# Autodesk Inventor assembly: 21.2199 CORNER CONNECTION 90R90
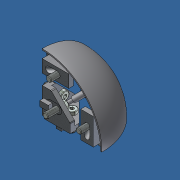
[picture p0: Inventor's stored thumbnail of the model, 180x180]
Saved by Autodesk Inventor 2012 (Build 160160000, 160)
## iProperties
Created: 2014-06
Part Number: 21.2199 CORNER CONNECTION 90R90
Document SubType Name: Assembly
Designer: Admin
Author: Admin
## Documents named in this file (7)
- C:\Andys Backup Data\ANDY'S INVENTOR\INVENTOR LIBRARIES\PARTS LIBRARY\FASTENING ELEMENTS\21.2199 CORNER CONNECTION 90R90.iam
- C:\Andys Backup Data\ANDY'S INVENTOR\INVENTOR LIBRARIES\PARTS LIBRARY\FASTENING ELEMENTS\SUBCOMPONENTS\22.0980_1 END CAP MW 90 R 90 GRAY.ipt
- C:\Andys Backup Data\ANDY'S INVENTOR\INVENTOR LIBRARIES\PARTS LIBRARY\FASTENING ELEMENTS\SUBCOMPONENTS\21.1708_2 ANGLE 45 DEG.ipt
- C:\Andys Backup Data\ANDY'S INVENTOR\INVENTOR LIBRARIES\PARTS LIBRARY\FASTENING ELEMENTS\SUBCOMPONENTS\21.1386 SCREW CON ANTI ROT.ipt
- C:\Andys Backup Data\ANDY'S INVENTOR\INVENTOR LIBRARIES\PARTS LIBRARY\FASTENING ELEMENTS\SCREWS CAP\21.1204 M8X25.ipt
- C:\Andys Backup Data\ANDY'S INVENTOR\INVENTOR LIBRARIES\PARTS LIBRARY\FASTENING ELEMENTS\SUBCOMPONENTS\21.2078_1 Angle 19.ipt
- C:\Andys Backup Data\ANDY'S INVENTOR\INVENTOR LIBRARIES\PARTS LIBRARY\FASTENING ELEMENTS\SCREWS CAP\21.1202 M8X20.ipt
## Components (17 placed, 6 different names)
1. 22.0980_1 END CAP MW 90 R 90 GRAY:1 — Mate:1, Flush:1
2. 21.1708_2 ANGLE 45 DEG:1 — Mate:1, Flush:1, Insert:1, Angle:1, Insert:2, Angle:2, Insert:3, Angle:3, Insert:4, Insert:5, Insert:6, Flush:2, Flush:3, Flush:4, Flush:5, Flush:6, Flush:7, Mate:22
3. 21.1386 SCREW CON ANTI ROT:1 — Insert:1, Angle:1
4. 21.1386 SCREW CON ANTI ROT:2 — Insert:3, Angle:3
5. 21.1386 SCREW CON ANTI ROT:3 — Insert:2, Angle:2
6. 21.1204  M8 x 25:1 — Insert:6
7. 21.1204  M8 x 25:2 — Insert:5, Mate:20, Mate:21
8. 21.1204  M8 x 25:3 — Insert:4
9. 21.2078_1 Angle 19:1 — Mate:14, Mate:15, Mate:16, Mate:17, Mate:18, Mate:19, Flush:4, Flush:5
10. 21.2078_1 Angle 19:2 — Mate:8, Mate:9, Mate:10, Mate:11, Mate:12, Mate:13, Flush:2, Flush:3
11. 21.2078_1 Angle 19:3 — Mate:2, Mate:3, Mate:4, Mate:5, Mate:6, Mate:7, Flush:6, Flush:7, Mate:22
12. 21.1202  M8 x 20:1 — Mate:5, Mate:6, Mate:7
13. 21.1202  M8 x 20:2 — Mate:14, Mate:16, Mate:19
14. 21.1202  M8 x 20:3 — Mate:15, Mate:17, Mate:18, Mate:21
15. 21.1202  M8 x 20:4 — Mate:11, Mate:12, Mate:13, Mate:20
16. 21.1202  M8 x 20:5 — Mate:2, Mate:3, Mate:4
17. 21.1202  M8 x 20:6 — Mate:8, Mate:9, Mate:10
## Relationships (38: Mate 22, Flush 7, Insert 6, Angle 3)
- Mate:1: 22.0980_1 END CAP MW 90 R 90 GRAY:1 ↔ 21.1708_2 ANGLE 45 DEG:1
- Flush:1: 22.0980_1 END CAP MW 90 R 90 GRAY:1 ↔ 21.1708_2 ANGLE 45 DEG:1
- Insert:1: 21.1708_2 ANGLE 45 DEG:1 ↔ 21.1386 SCREW CON ANTI ROT:1
- Angle:1: 21.1708_2 ANGLE 45 DEG:1 ↔ 21.1386 SCREW CON ANTI ROT:1
- Insert:2: 21.1708_2 ANGLE 45 DEG:1 ↔ 21.1386 SCREW CON ANTI ROT:3
- Angle:2: 21.1708_2 ANGLE 45 DEG:1 ↔ 21.1386 SCREW CON ANTI ROT:3
- Insert:3: 21.1708_2 ANGLE 45 DEG:1 ↔ 21.1386 SCREW CON ANTI ROT:2
- Angle:3: 21.1708_2 ANGLE 45 DEG:1 ↔ 21.1386 SCREW CON ANTI ROT:2
- Insert:4: 21.1708_2 ANGLE 45 DEG:1 ↔ 21.1204  M8 x 25:3
- Insert:5: 21.1708_2 ANGLE 45 DEG:1 ↔ 21.1204  M8 x 25:2
- Insert:6: 21.1708_2 ANGLE 45 DEG:1 ↔ 21.1204  M8 x 25:1
- Mate:2: 21.2078_1 Angle 19:3 ↔ 21.1202  M8 x 20:5
- Mate:3: 21.2078_1 Angle 19:3 ↔ 21.1202  M8 x 20:5
- Mate:4: 21.2078_1 Angle 19:3 ↔ 21.1202  M8 x 20:5
- Mate:5: 21.2078_1 Angle 19:3 ↔ 21.1202  M8 x 20:1
- Mate:6: 21.2078_1 Angle 19:3 ↔ 21.1202  M8 x 20:1
- Mate:7: 21.2078_1 Angle 19:3 ↔ 21.1202  M8 x 20:1
- Mate:8: 21.2078_1 Angle 19:2 ↔ 21.1202  M8 x 20:6
- Mate:9: 21.2078_1 Angle 19:2 ↔ 21.1202  M8 x 20:6
- Mate:10: 21.2078_1 Angle 19:2 ↔ 21.1202  M8 x 20:6
- Mate:11: 21.2078_1 Angle 19:2 ↔ 21.1202  M8 x 20:4
- Mate:12: 21.2078_1 Angle 19:2 ↔ 21.1202  M8 x 20:4
- Mate:13: 21.2078_1 Angle 19:2 ↔ 21.1202  M8 x 20:4
- Mate:14: 21.2078_1 Angle 19:1 ↔ 21.1202  M8 x 20:2
- Mate:15: 21.2078_1 Angle 19:1 ↔ 21.1202  M8 x 20:3
- Mate:16: 21.2078_1 Angle 19:1 ↔ 21.1202  M8 x 20:2
- Mate:17: 21.2078_1 Angle 19:1 ↔ 21.1202  M8 x 20:3
- Mate:18: 21.2078_1 Angle 19:1 ↔ 21.1202  M8 x 20:3
- Mate:19: 21.2078_1 Angle 19:1 ↔ 21.1202  M8 x 20:2
- Flush:2: 21.1708_2 ANGLE 45 DEG:1 ↔ 21.2078_1 Angle 19:2
- Flush:3: 21.1708_2 ANGLE 45 DEG:1 ↔ 21.2078_1 Angle 19:2
- Mate:20: 21.1204  M8 x 25:2 ↔ 21.1202  M8 x 20:4
- Flush:4: 21.1708_2 ANGLE 45 DEG:1 ↔ 21.2078_1 Angle 19:1
- Flush:5: 21.1708_2 ANGLE 45 DEG:1 ↔ 21.2078_1 Angle 19:1
- Mate:21: 21.1204  M8 x 25:2 ↔ 21.1202  M8 x 20:3
- Flush:6: 21.1708_2 ANGLE 45 DEG:1 ↔ 21.2078_1 Angle 19:3
- Flush:7: 21.1708_2 ANGLE 45 DEG:1 ↔ 21.2078_1 Angle 19:3
- Mate:22: 21.1708_2 ANGLE 45 DEG:1 ↔ 21.2078_1 Angle 19:3
